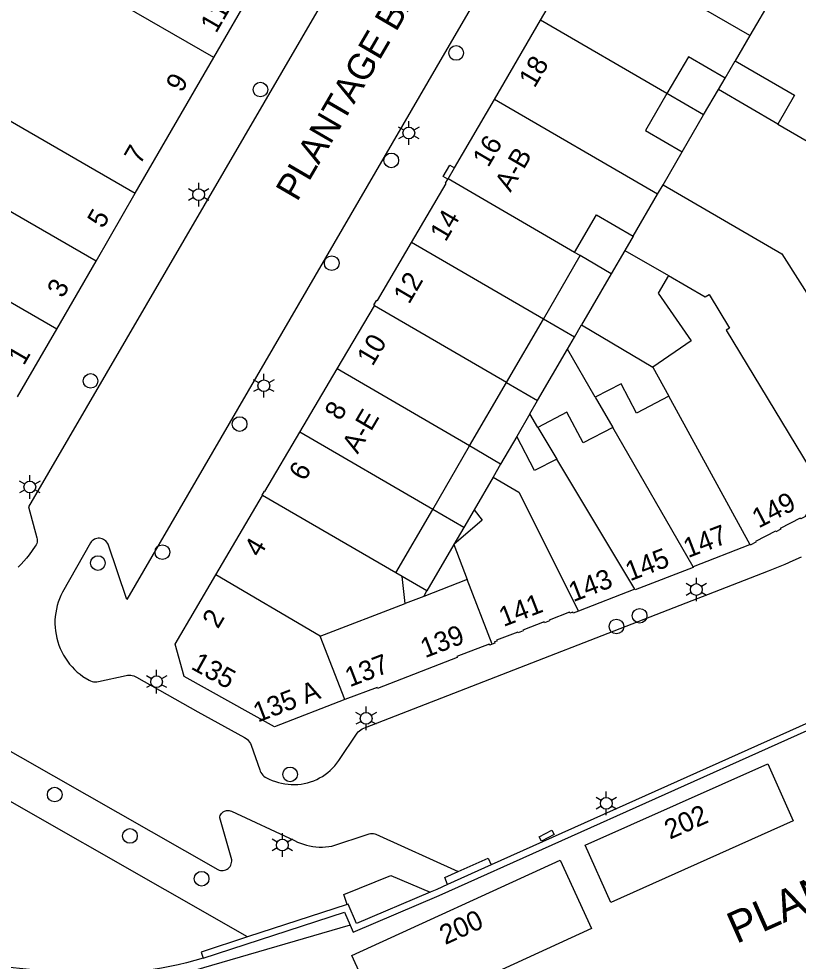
# Model space of a CAD drawing. Extents: x 122462 to 123306, y 485548 to 486417.
# Drawn here: x 122924.9 to 122984.4, y 486281.1 to 486353 of the extents above; entities that cross this region are included whole.
import ezdxf

# ---------------------------------------------------------------- set-up
doc = ezdxf.new("R2010")
doc.units = 0
for name, color, linetype in [('Level 1', 7, 'Continuous'), ('Level 12', 7, 'Continuous'), ('Level 15', 7, 'Continuous'), ('Level 16', 7, 'Continuous'), ('Level 17', 7, 'Continuous'), ('Level 19', 7, 'Continuous'), ('Level 4', 7, 'Continuous'), ('Level 40', 7, 'Continuous'), ('Level 50', 7, 'Continuous'), ('Level 53', 7, 'Continuous'), ('Level 58', 7, 'Continuous'), ('Level 59', 7, 'Continuous'), ('Level 60', 7, 'Continuous')]:
    doc.layers.add(name, color=color, linetype=linetype)

msp = doc.modelspace()

# ---------------------------------------------------------------- linework, layer by layer
at = {"layer": 'Level 1'}
for p, q in [((122964.734, 486352.951), (122968.264, 486359.007)), ((122982.598, 486355.009), (122980.712, 486351.767)), ((122961.204, 486346.895), (122964.734, 486352.951)), ((122980.712, 486351.767), (122979.595, 486349.847)), ((122933.779, 486339.729), (122939.778, 486350.092)), ((122978.313, 486347.642), (122978.827, 486348.526)), ((122977.188, 486345.708), (122978.313, 486347.642)), ((122958.152, 486341.659), (122961.204, 486346.895)), ((122975.554, 486342.898), (122977.188, 486345.708)), ((122982.847, 486345.005), (122988.24, 486341.869)), ((122957.67, 486340.84), (122958.152, 486341.659)), ((122957.648, 486340.795), (122957.67, 486340.84)), ((122930.78, 486334.545), (122933.779, 486339.729)), ((122971.802, 486336.446), (122971.175, 486335.369)), ((122967.769, 486334.965), (122967.337, 486335.217)), ((122971.175, 486335.369), (122974.493, 486333.439)), ((122927.779, 486329.36), (122930.78, 486334.545)), ((122964.952, 486330.121), (122967.769, 486334.965)), ((122949.199, 486326.315), (122952.049, 486331.142)), ((122962.133, 486325.275), (122964.952, 486330.121)), ((122924.78, 486324.189), (122927.779, 486329.36)), ((122973.313, 486326.446), (122974.525, 486324.234)), ((122946.348, 486321.488), (122949.199, 486326.315)), ((122959.315, 486320.43), (122962.133, 486325.275)), ((122968.91, 486324.146), (122970.24, 486321.839)), ((122964.528, 486321.853), (122965.973, 486319.435)), ((122962.908, 486321.155), (122961.684, 486319.052)), ((122956.496, 486315.584), (122959.315, 486320.43)), ((122961.684, 486319.052), (122961.107, 486318.06)), ((122961.107, 486318.06), (122959.656, 486315.566)), ((122939.929, 486310.579), (122943.495, 486316.659)), ((122953.677, 486310.737), (122956.496, 486315.584)), ((122958.107, 486312.901), (122959.137, 486310.235)), ((122954.166, 486310.452), (122953.677, 486310.737)), ((122954.394, 486308.403), (122954.166, 486310.452)), ((122959.137, 486310.235), (122955.809, 486308.949)), ((122971.938, 486309.497), (122967.63, 486307.829)), ((122955.809, 486308.949), (122954.394, 486308.403))]:
    msp.add_line(p, q, dxfattribs=at)
for points in [[(122939.778, 486350.092), (122942.767, 486355.255), (122942.809, 486355.229), (122942.93, 486355.445)], [(122978.827, 486348.526), (122976.026, 486350.155), (122974.386, 486347.337)], [(122979.595, 486349.847), (122984.129, 486347.209), (122982.847, 486345.005)], [(122974.386, 486347.337), (122972.753, 486344.527), (122975.554, 486342.898)], [(122954.885, 486335.978), (122957.516, 486340.463), (122957.469, 486340.489), (122957.648, 486340.795)], [(122967.337, 486335.217), (122969, 486338.076), (122971.802, 486336.446)], [(122952.049, 486331.142), (122952.064, 486331.168), (122952.009, 486331.199), (122952.229, 486331.559), (122952.278, 486331.532), (122954.885, 486335.978)], [(122974.493, 486333.439), (122973.716, 486332.102), (122976.231, 486328.463), (122973.313, 486326.446)], [(122974.525, 486324.234), (122972.058, 486322.943), (122970.887, 486325.181), (122968.91, 486324.146)], [(122970.24, 486321.839), (122967.985, 486320.659), (122966.751, 486323.016), (122964.528, 486321.853)], [(122943.495, 486316.659), (122943.459, 486316.679), (122943.637, 486316.98), (122943.673, 486316.959), (122946.348, 486321.488)], [(122965.973, 486319.435), (122964.274, 486318.546), (122962.908, 486321.155)], [(122959.656, 486315.566), (122960.279, 486314.771), (122958.107, 486312.901)], [(122986.856, 486316.174), (122986.91, 486316.079), (122986.87, 486316.029), (122986.505, 486315.841), (122986.472, 486315.904), (122984.944, 486315.114), (122984.977, 486315.05), (122984.604, 486314.857), (122984.571, 486314.921), (122983.043, 486314.13), (122983.075, 486314.067), (122982.701, 486313.874), (122982.669, 486313.936), (122981.141, 486313.146), (122981.173, 486313.083), (122980.799, 486312.89), (122980.745, 486312.88)], [(122980.745, 486312.88), (122980.689, 486312.87), (122976.376, 486311.202)], [(122949.779, 486301.059), (122944.42, 486298.989), (122937.509, 486302.84), (122936.83, 486305.299), (122939.929, 486310.579)], [(122976.376, 486311.202), (122976.4, 486311.14), (122971.959, 486309.439), (122971.938, 486309.497)], [(122967.63, 486307.829), (122967.219, 486307.674), (122967.189, 486307.749), (122966.976, 486307.668), (122966.951, 486307.734), (122965.4, 486307.141), (122965.425, 486307.075), (122965.032, 486306.924), (122965.007, 486306.99), (122963.381, 486306.368), (122963.407, 486306.302), (122963.013, 486306.151), (122962.988, 486306.217), (122961.372, 486305.598), (122961.397, 486305.532), (122961.215, 486305.462), (122961.249, 486305.37), (122961.045, 486305.293)], [(122961.045, 486305.293), (122960.85, 486305.219), (122960.82, 486305.3), (122958.34, 486304.35), (122958.37, 486304.269), (122952.289, 486301.91), (122952.25, 486302), (122949.779, 486301.059)]]:
    msp.add_lwpolyline(points, dxfattribs=at)
at = {"layer": 'Level 12'}
for points in [[(122970.095, 486285.577), (122968.147, 486289.939), (122982.085, 486296.166), (122984.034, 486291.803), (122970.095, 486285.577)], [(122952.713, 486276.288), (122950.317, 486281.521), (122966.237, 486288.809), (122968.633, 486283.576), (122952.713, 486276.288)]]:
    msp.add_lwpolyline(points, dxfattribs=at)
at = {"layer": 'Level 15'}
for p, q in [((122960.966, 486288.441), (122957.624, 486286.944)), ((122949.962, 486285.428), (122942.359, 486282.948))]:
    msp.add_line(p, q, dxfattribs=at)
for points in [[(122990.105, 486303.459), (122990.85, 486301.824), (122960.966, 486288.441)], [(122950.181, 486283.839), (122950.413, 486283.298), (122957.001, 486286.117), (122991.513, 486301.574), (122991.016, 486302.666)], [(122957.624, 486286.944), (122956.8, 486286.575), (122956.293, 486286.358)], [(122956.293, 486286.358), (122950.676, 486283.954), (122950.034, 486285.451), (122949.962, 486285.428)], [(122938.958, 486281.32), (122949.755, 486284.834), (122950.181, 486283.839)], [(122942.359, 486282.948), (122938.805, 486281.789), (122938.958, 486281.32)]]:
    msp.add_lwpolyline(points, dxfattribs=at)
at = {"layer": 'Level 16'}
msp.add_lwpolyline([(122950.181, 486283.839), (122938.2, 486280.349), (122937.478, 486280.151), (122936.752, 486279.968), (122936.022, 486279.8), (122935.289, 486279.648), (122934.553, 486279.511), (122933.814, 486279.389), (122933.073, 486279.282), (122932.33, 486279.191), (122931.585, 486279.115), (122930.838, 486279.055), (122930.091, 486279.011), (122929.343, 486278.982), (122928.594, 486278.968), (122927.845, 486278.97), (122927.096, 486278.988), (122926.348, 486279.021), (122925.601, 486279.07), (122924.855, 486279.135)], dxfattribs=at)
at = {"layer": 'Level 17'}
for points in [[(122967.757, 486368.219), (122956.772, 486349.34), (122933.127, 486308.701), (122931.696, 486312.927), (122931.649, 486313.019), (122931.59, 486313.103), (122931.52, 486313.179), (122931.44, 486313.245), (122931.352, 486313.299), (122931.257, 486313.34), (122931.158, 486313.369), (122931.056, 486313.383), (122930.953, 486313.384), (122930.85, 486313.37), (122930.751, 486313.343), (122930.656, 486313.302), (122930.567, 486313.249), (122930.487, 486313.184), (122930.416, 486313.109), (122930.356, 486313.025), (122928.225, 486309.272), (122928.101, 486309.022), (122927.992, 486308.766), (122927.897, 486308.504), (122927.817, 486308.237), (122927.751, 486307.966), (122927.701, 486307.691), (122927.667, 486307.415), (122927.647, 486307.137), (122927.644, 486306.858), (122927.655, 486306.579), (122927.683, 486306.302), (122927.725, 486306.026), (122927.783, 486305.754), (122927.857, 486305.485), (122927.945, 486305.22), (122928.047, 486304.961), (122928.164, 486304.708), (122928.295, 486304.462), (122928.439, 486304.223), (122928.596, 486303.993), (122928.766, 486303.772), (122928.948, 486303.561), (122929.142, 486303.36), (122929.346, 486303.171), (122929.561, 486302.993), (122929.785, 486302.827), (122930.25, 486302.555), (122930.361, 486302.499), (122930.479, 486302.457), (122930.6, 486302.43), (122930.724, 486302.418), (122930.849, 486302.422), (122930.972, 486302.442), (122933.076, 486302.91), (122933.194, 486302.926), (122933.312, 486302.93), (122933.431, 486302.922), (122933.548, 486302.903), (122933.663, 486302.872), (122933.774, 486302.83), (122933.88, 486302.777), (122938.557, 486300.123), (122942.133, 486298.173), (122942.243, 486298.103), (122942.344, 486298.021), (122942.435, 486297.927), (122942.514, 486297.823), (122942.58, 486297.71), (122942.632, 486297.59), (122943.285, 486295.695), (122943.327, 486295.588), (122943.38, 486295.485), (122943.444, 486295.389), (122943.519, 486295.301), (122943.602, 486295.221), (122943.693, 486295.151), (122943.792, 486295.091), (122944.015, 486294.983), (122944.244, 486294.888), (122944.478, 486294.805), (122944.715, 486294.735), (122944.956, 486294.678), (122945.2, 486294.634), (122945.446, 486294.604), (122945.693, 486294.586), (122945.941, 486294.582), (122946.189, 486294.592), (122946.438, 486294.618), (122946.684, 486294.658), (122946.928, 486294.714), (122947.169, 486294.784), (122947.404, 486294.868), (122947.634, 486294.966), (122947.858, 486295.078), (122948.074, 486295.204), (122948.283, 486295.342), (122948.483, 486295.492), (122948.673, 486295.654)], [(122947.99, 486354.186), (122925.615, 486315.795), (122926.271, 486313.423), (122926.289, 486313.311), (122926.291, 486313.198), (122926.277, 486313.086), (122926.248, 486312.977), (122926.203, 486312.873), (122926.145, 486312.776), (122925.67, 486312.106), (122925.477, 486311.86), (122925.272, 486311.622), (122925.057, 486311.395), (122924.832, 486311.177)], [(122948.673, 486295.654), (122948.854, 486295.828), (122949.023, 486296.012), (122949.182, 486296.205), (122949.328, 486296.408), (122950.732, 486298.492), (122950.81, 486298.594), (122950.901, 486298.686), (122951.001, 486298.766), (122951.111, 486298.833), (122951.228, 486298.887), (122951.351, 486298.927), (122982.131, 486310.897), (122982.771, 486311.147), (122983.406, 486311.409), (122984.036, 486311.683), (122984.661, 486311.969)], [(122942.359, 486282.948), (122917.343, 486297.21), (122916.175, 486301.938), (122913.236, 486303.578)], [(122922.411, 486298.136), (122940.082, 486288.092), (122940.179, 486288.05), (122940.282, 486288.023), (122940.387, 486288.011), (122940.493, 486288.014), (122940.597, 486288.033), (122940.697, 486288.066), (122940.792, 486288.114), (122940.879, 486288.175), (122940.956, 486288.248), (122941.021, 486288.331), (122941.074, 486288.422), (122941.113, 486288.521), (122941.138, 486288.624), (122941.147, 486288.729), (122941.141, 486288.835), (122940.229, 486292.032), (122940.244, 486292.123), (122940.272, 486292.212), (122940.312, 486292.295), (122940.365, 486292.371), (122940.428, 486292.439), (122940.501, 486292.496), (122940.581, 486292.543), (122940.667, 486292.576), (122940.757, 486292.597), (122940.85, 486292.605), (122940.942, 486292.598), (122941.033, 486292.578), (122941.119, 486292.545), (122945.941, 486290.293), (122946.162, 486290.187), (122946.388, 486290.094), (122946.619, 486290.013), (122946.854, 486289.945), (122947.093, 486289.89), (122947.334, 486289.848), (122947.577, 486289.82), (122947.822, 486289.805), (122948.067, 486289.804), (122948.311, 486289.816), (122948.555, 486289.842), (122948.796, 486289.881), (122951.555, 486290.784), (122951.653, 486290.816), (122951.755, 486290.835), (122951.858, 486290.842), (122951.961, 486290.835)], [(122951.961, 486290.835), (122952.063, 486290.816), (122952.162, 486290.785), (122958.448, 486287.941)], [(122958.448, 486287.941), (122960.736, 486288.946), (122960.966, 486288.441)], [(122949.962, 486285.428), (122949.701, 486286.177), (122953.296, 486287.642), (122956.293, 486286.358)], [(122957.624, 486286.944), (122957.421, 486287.489), (122958.448, 486287.941)]]:
    msp.add_lwpolyline(points, dxfattribs=at)
at = {"layer": 'Level 19'}
for p, q in [((122977.188, 486345.708), (122974.386, 486347.337)), ((122971.175, 486335.369), (122970.138, 486333.587)), ((122970.138, 486333.587), (122967.769, 486334.965)), ((122970.138, 486333.587), (122967.864, 486329.677)), ((122967.321, 486328.743), (122964.952, 486330.121)), ((122967.321, 486328.743), (122967.864, 486329.677)), ((122967.864, 486329.677), (122973.313, 486326.446)), ((122966.789, 486327.827), (122967.321, 486328.743)), ((122964.503, 486323.897), (122966.789, 486327.827)), ((122968.91, 486324.146), (122966.789, 486327.827)), ((122962.133, 486325.275), (122964.503, 486323.897)), ((122963.913, 486322.883), (122964.503, 486323.897)), ((122963.913, 486322.883), (122962.908, 486321.155)), ((122964.528, 486321.853), (122963.913, 486322.883)), ((122961.684, 486319.052), (122959.315, 486320.43)), ((122958.865, 486314.205), (122956.496, 486315.584)), ((122959.656, 486315.566), (122958.865, 486314.205)), ((122958.865, 486314.205), (122958.107, 486312.901)), ((122958.107, 486312.901), (122956.047, 486309.359)), ((122956.047, 486309.359), (122954.166, 486310.452)), ((122955.809, 486308.949), (122956.047, 486309.359))]:
    msp.add_line(p, q, dxfattribs=at)
msp.add_lwpolyline([(122938.958, 486281.32), (122938.331, 486281.138), (122937.699, 486280.97), (122937.064, 486280.817), (122936.426, 486280.679), (122935.785, 486280.555), (122935.141, 486280.446), (122934.494, 486280.352), (122933.846, 486280.273), (122933.196, 486280.208), (122932.545, 486280.159), (122931.892, 486280.125), (122931.24, 486280.106), (122930.586, 486280.102), (122929.933, 486280.112), (122929.281, 486280.138), (122928.629, 486280.179), (122927.978, 486280.235), (122921.409, 486280.874), (122912.909, 486282.251)], dxfattribs=at)
at = {"layer": 'Level 4'}
for p, q in [((122980.712, 486351.767), (122968.264, 486359.007)), ((122939.778, 486350.092), (122928.297, 486356.717)), ((122974.386, 486347.337), (122964.734, 486352.951)), ((122978.827, 486348.526), (122979.595, 486349.847)), ((122982.847, 486345.005), (122978.313, 486347.642)), ((122973.664, 486339.647), (122961.204, 486346.895)), ((122922.442, 486346.272), (122933.779, 486339.729)), ((122974.087, 486340.375), (122975.554, 486342.898)), ((122930.78, 486334.545), (122919.448, 486341.083)), ((122967.337, 486335.217), (122957.67, 486340.84)), ((122973.664, 486339.647), (122974.087, 486340.375)), ((122971.802, 486336.446), (122973.664, 486339.647)), ((122927.779, 486329.36), (122916.454, 486335.895)), ((122964.952, 486330.121), (122954.885, 486335.978)), ((122962.133, 486325.275), (122952.049, 486331.142)), ((122959.315, 486320.43), (122949.199, 486326.315)), ((122980.745, 486312.88), (122974.525, 486324.234)), ((122956.496, 486315.584), (122946.348, 486321.488)), ((122976.376, 486311.202), (122970.24, 486321.839)), ((122971.938, 486309.497), (122965.973, 486319.435)), ((122953.677, 486310.737), (122943.495, 486316.659)), ((122947.911, 486305.899), (122939.929, 486310.579)), ((122961.045, 486305.293), (122959.137, 486310.235)), ((122947.911, 486305.899), (122954.394, 486308.403)), ((122949.779, 486301.059), (122947.911, 486305.899))]:
    msp.add_line(p, q, dxfattribs=at)
for points in [[(122974.087, 486340.375), (122983.156, 486335.1), (122992.78, 486319.955)], [(122974.493, 486333.439), (122977.293, 486331.81), (122977.604, 486331.998), (122979.168, 486329.421), (122978.909, 486329.264), (122986.856, 486316.174)], [(122961.107, 486318.06), (122963.084, 486316.91), (122967.63, 486307.829)]]:
    msp.add_lwpolyline(points, dxfattribs=at)
at = {"layer": 'Level 40'}
for points in [[(122957.648, 486340.795), (122957.299, 486340.999), (122957.803, 486341.863), (122958.152, 486341.659)], [(122964.799, 486290.248), (122964.626, 486290.572), (122965.603, 486291.093), (122965.775, 486290.77), (122964.799, 486290.248)]]:
    msp.add_lwpolyline(points, dxfattribs=at)
at = {"layer": 'Level 50'}
for p, q in [((122954.67, 486344.782), (122954.67, 486345.232)), ((122954.28, 486344.557), (122953.89, 486344.782)), ((122955.449, 486344.782), (122955.059, 486344.557)), ((122954.28, 486344.107), (122953.89, 486343.882)), ((122954.67, 486343.432), (122954.67, 486343.882)), ((122955.449, 486343.882), (122955.059, 486344.107)), ((122938.232, 486339.849), (122937.842, 486340.074)), ((122938.622, 486340.074), (122938.622, 486340.524)), ((122939.401, 486340.074), (122939.011, 486339.849)), ((122938.232, 486339.399), (122937.842, 486339.174)), ((122939.401, 486339.174), (122939.011, 486339.399)), ((122938.622, 486338.724), (122938.622, 486339.174)), ((122943.598, 486325.478), (122943.598, 486325.928)), ((122943.208, 486325.253), (122942.818, 486325.478)), ((122944.377, 486325.478), (122943.987, 486325.253)), ((122943.208, 486324.803), (122942.818, 486324.578)), ((122943.598, 486324.128), (122943.598, 486324.578)), ((122944.377, 486324.578), (122943.987, 486324.803)), ((122925.333, 486317.524), (122924.943, 486317.749)), ((122925.723, 486317.749), (122925.723, 486318.199)), ((122926.502, 486317.749), (122926.112, 486317.524)), ((122925.333, 486317.074), (122924.943, 486316.849)), ((122926.502, 486316.849), (122926.112, 486317.074)), ((122925.723, 486316.399), (122925.723, 486316.849)), ((122976.242, 486309.693), (122975.852, 486309.918)), ((122976.632, 486309.918), (122976.632, 486310.368)), ((122977.411, 486309.918), (122977.021, 486309.693)), ((122976.242, 486309.243), (122975.852, 486309.018)), ((122977.411, 486309.018), (122977.021, 486309.243)), ((122976.632, 486308.568), (122976.632, 486309.018)), ((122935.014, 486302.651), (122934.624, 486302.876)), ((122935.404, 486302.876), (122935.404, 486303.326)), ((122936.183, 486302.876), (122935.793, 486302.651)), ((122935.014, 486302.201), (122934.624, 486301.976)), ((122935.404, 486301.526), (122935.404, 486301.976)), ((122936.183, 486301.976), (122935.793, 486302.201)), ((122951.411, 486300.077), (122951.411, 486300.527)), ((122951.021, 486299.852), (122950.631, 486300.077)), ((122952.19, 486300.077), (122951.8, 486299.852)), ((122951.021, 486299.402), (122950.631, 486299.177)), ((122951.411, 486298.727), (122951.411, 486299.177)), ((122952.19, 486299.177), (122951.8, 486299.402)), ((122969.753, 486293.592), (122969.753, 486294.042)), ((122969.363, 486293.367), (122968.973, 486293.592)), ((122970.532, 486293.592), (122970.142, 486293.367)), ((122969.363, 486292.917), (122968.973, 486292.692)), ((122969.753, 486292.242), (122969.753, 486292.692)), ((122970.532, 486292.692), (122970.142, 486292.917)), ((122944.623, 486290.182), (122944.233, 486290.407)), ((122945.013, 486290.407), (122945.013, 486290.857)), ((122945.792, 486290.407), (122945.402, 486290.182)), ((122944.623, 486289.732), (122944.233, 486289.507)), ((122945.792, 486289.507), (122945.402, 486289.732)), ((122945.013, 486289.057), (122945.013, 486289.507))]:
    msp.add_line(p, q, dxfattribs=at)
for centre in [(122954.67, 486344.332), (122938.622, 486339.624), (122943.598, 486325.028), (122925.723, 486317.299), (122976.632, 486309.468), (122935.404, 486302.426), (122951.411, 486299.627), (122969.753, 486293.142), (122945.013, 486289.957)]:
    msp.add_circle(centre, 0.45, dxfattribs=at)
at = {"layer": 'Level 53'}
for centre in [(122958.288, 486350.44), (122943.341, 486347.649), (122953.334, 486342.242), (122948.779, 486334.39), (122930.363, 486325.403), (122941.747, 486322.106), (122935.851, 486312.323), (122930.924, 486311.494), (122972.297, 486307.464), (122970.528, 486306.646), (122945.606, 486295.353), (122927.623, 486293.814), (122933.372, 486290.653), (122938.843, 486287.383)]:
    msp.add_circle(centre, 0.56, dxfattribs=at)

# ---------------------------------------------------------------- texts
at = {"layer": 'Level 58'}
for s, rotation, p in [('11', 59.93901, (122939.952, 486351.887)), ('18', 59.51267, (122964.273, 486347.705)), ('9', 59.93901, (122937.324, 486347.348)), ('16', 59.51267, (122960.738, 486341.64)), ('7', 59.93901, (122934.142, 486341.852)), ('A-B', 59.76024, (122962.436, 486339.755)), ('5', 59.93901, (122931.318, 486336.974)), ('14', 59.51267, (122957.48, 486335.96)), ('12', 59.51267, (122954.687, 486331.196)), ('3', 59.94038, (122928.241, 486331.654)), ('10', 59.51267, (122951.903, 486326.464)), ('1', 59.91219, (122925.266, 486326.521)), ('8', 59.51267, (122949.435, 486322.29)), ('A-E', 59.43239, (122950.763, 486319.761)), ('6', 59.51267, (122946.713, 486317.681)), ('149', 27.35072, (122981.386, 486314.118)), ('147', 21.03964, (122975.999, 486311.864)), ('4', 59.51267, (122943.29, 486311.865)), ('145', 21.03964, (122971.567, 486310.09)), ('143', 21.03964, (122967.235, 486308.504)), ('141', 21.03964, (122961.909, 486306.604)), ('2', 59.51267, (122940.091, 486306.411)), ('139', 21.03964, (122955.914, 486304.221)), ('135', 330.88032, (122937.957, 486303.452)), ('137', 21.03964, (122950.155, 486301.997)), ('135 A', 21.03964, (122943.144, 486299.307)), ('202', 24.07338, (122974.609, 486290.362)), ('200', 24.59778, (122957.453, 486282.313))]:
    msp.add_text(s, height=1.5, rotation=rotation, dxfattribs=at).set_placement(p)
at = {"layer": 'Level 59'}
msp.add_text('PLANTAGE BADLAAN', height=2, rotation=59.78895, dxfattribs=at).set_placement((122946.139, 486339.024))
at = {"layer": 'Level 60'}
msp.add_text('PLANTAGE MUIDERGRACHT', height=2.4, rotation=23.89907, dxfattribs=at).set_placement((122979.688, 486282.392))

doc.saveas('drawing.dxf')
